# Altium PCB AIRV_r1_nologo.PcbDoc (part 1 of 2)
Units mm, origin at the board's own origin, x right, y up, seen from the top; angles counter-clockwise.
Board outline 65 x 30 mm, 4 copper layers (Top Layer, GND, MidLayer1, Bottom Layer), stack 0.732 mm thick; 130 components, 121 nets, 598 pads, 392 vias.
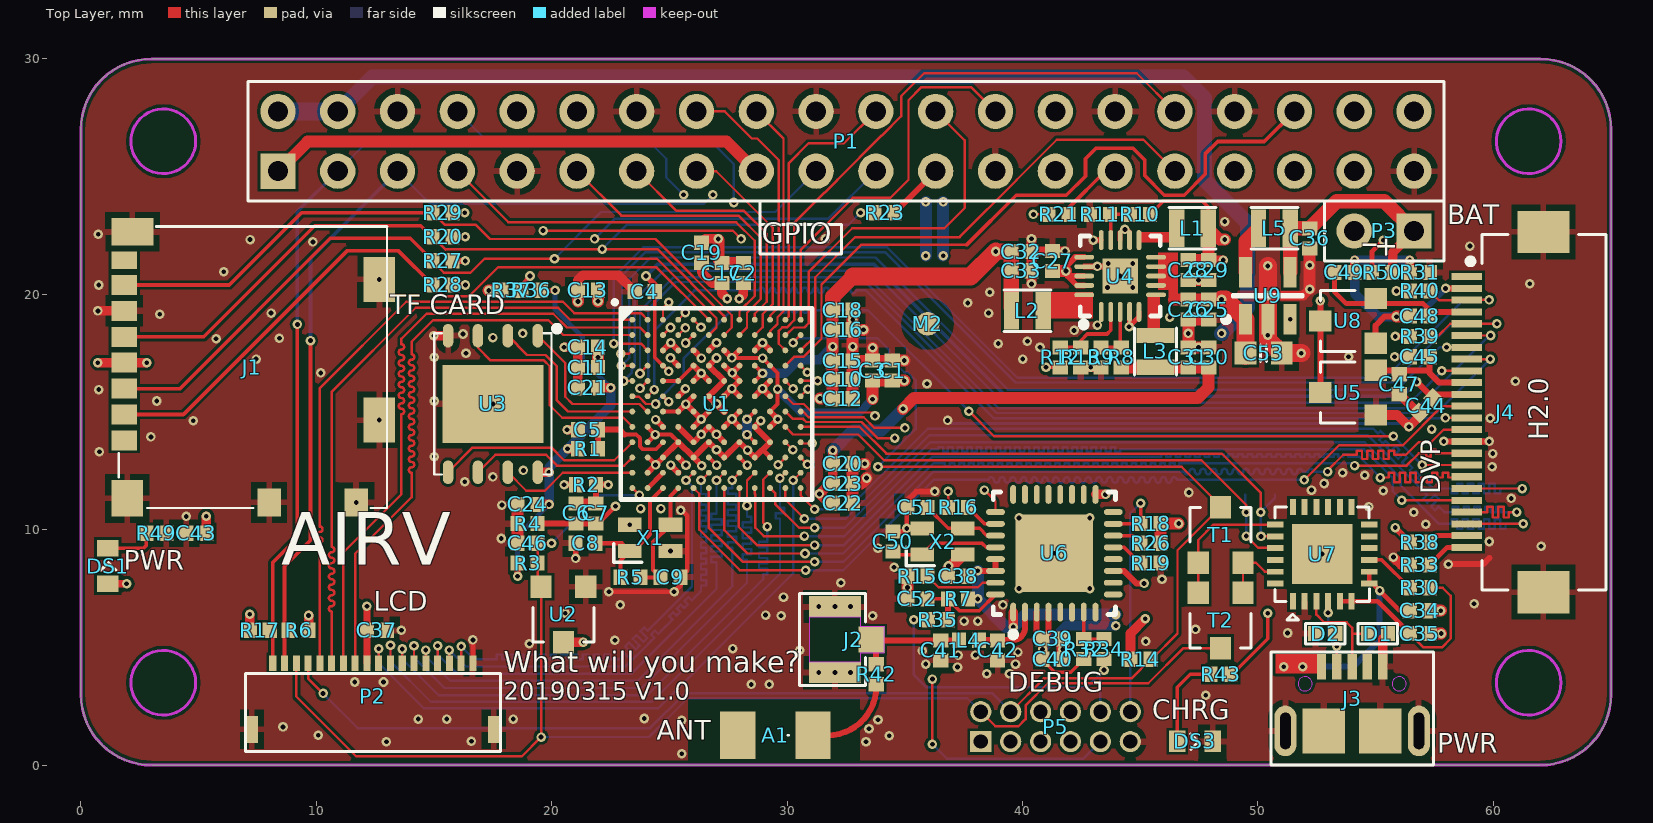
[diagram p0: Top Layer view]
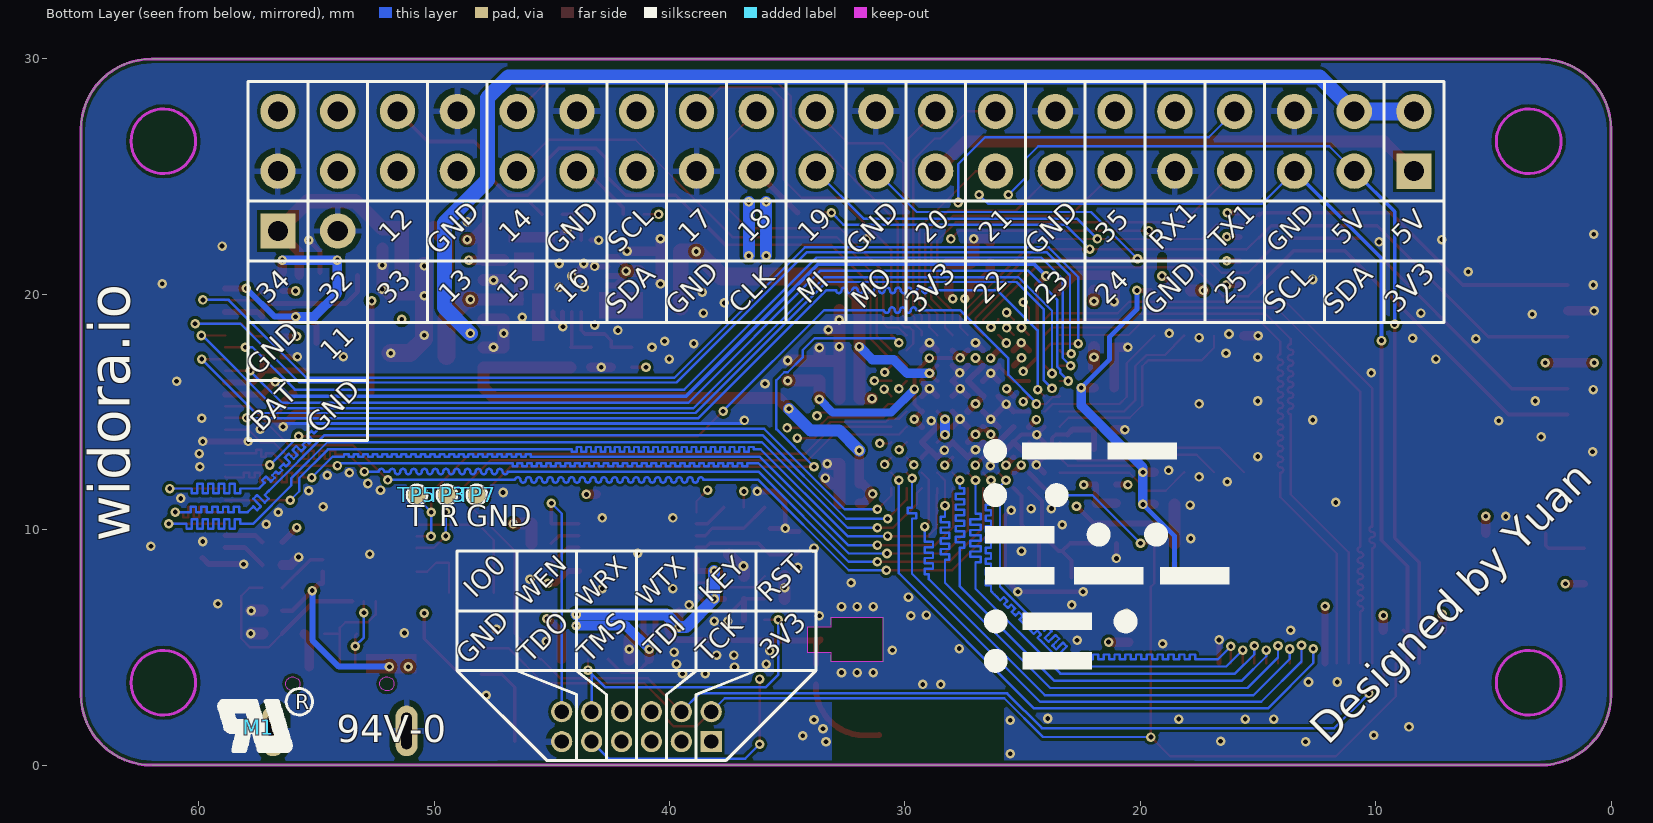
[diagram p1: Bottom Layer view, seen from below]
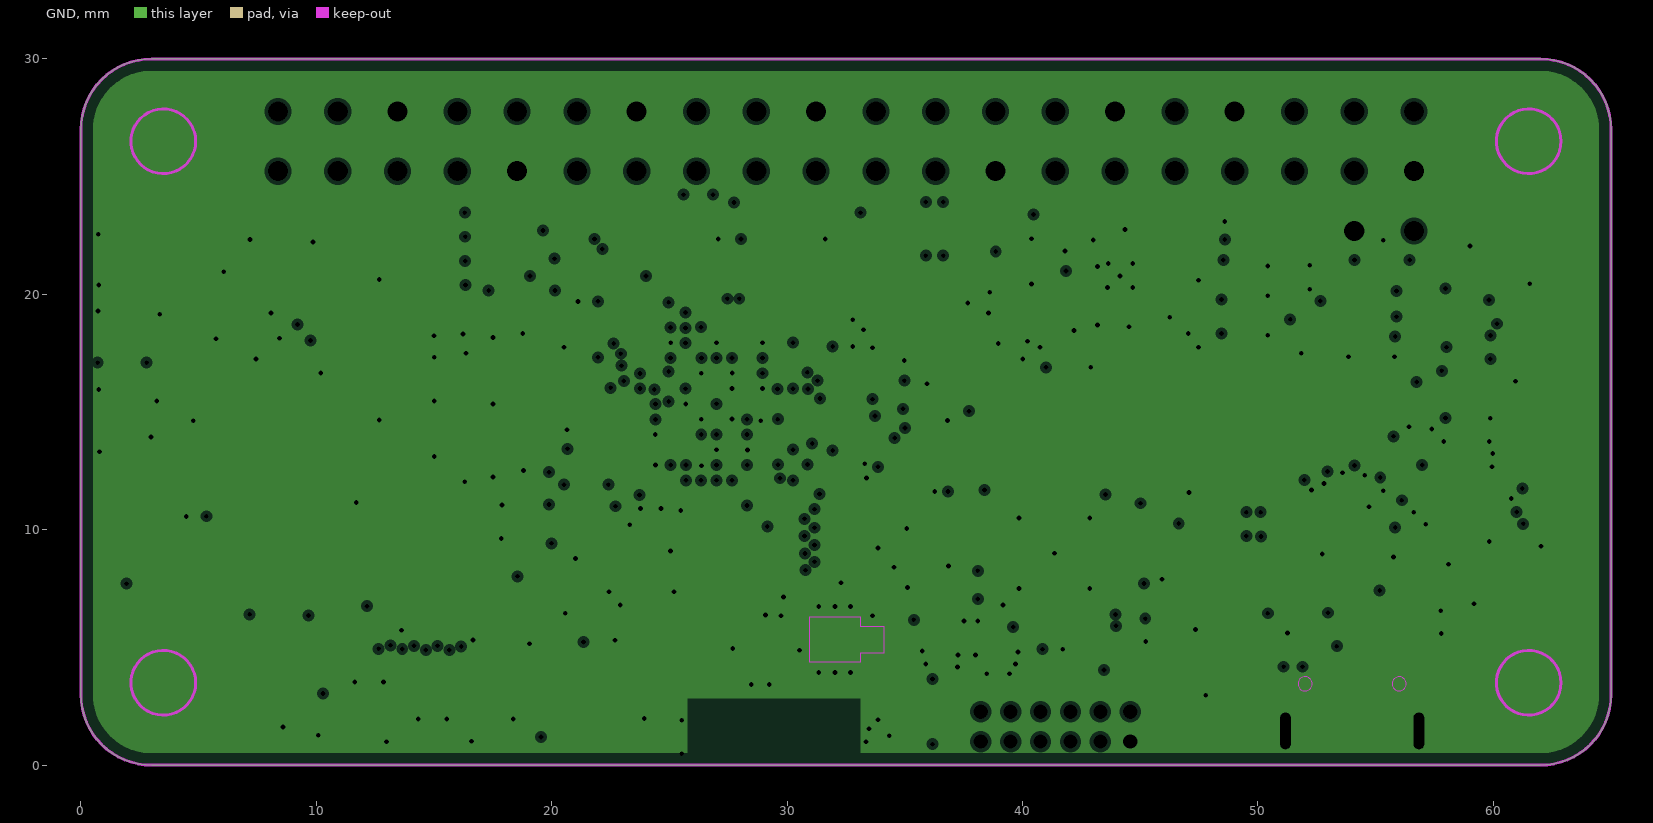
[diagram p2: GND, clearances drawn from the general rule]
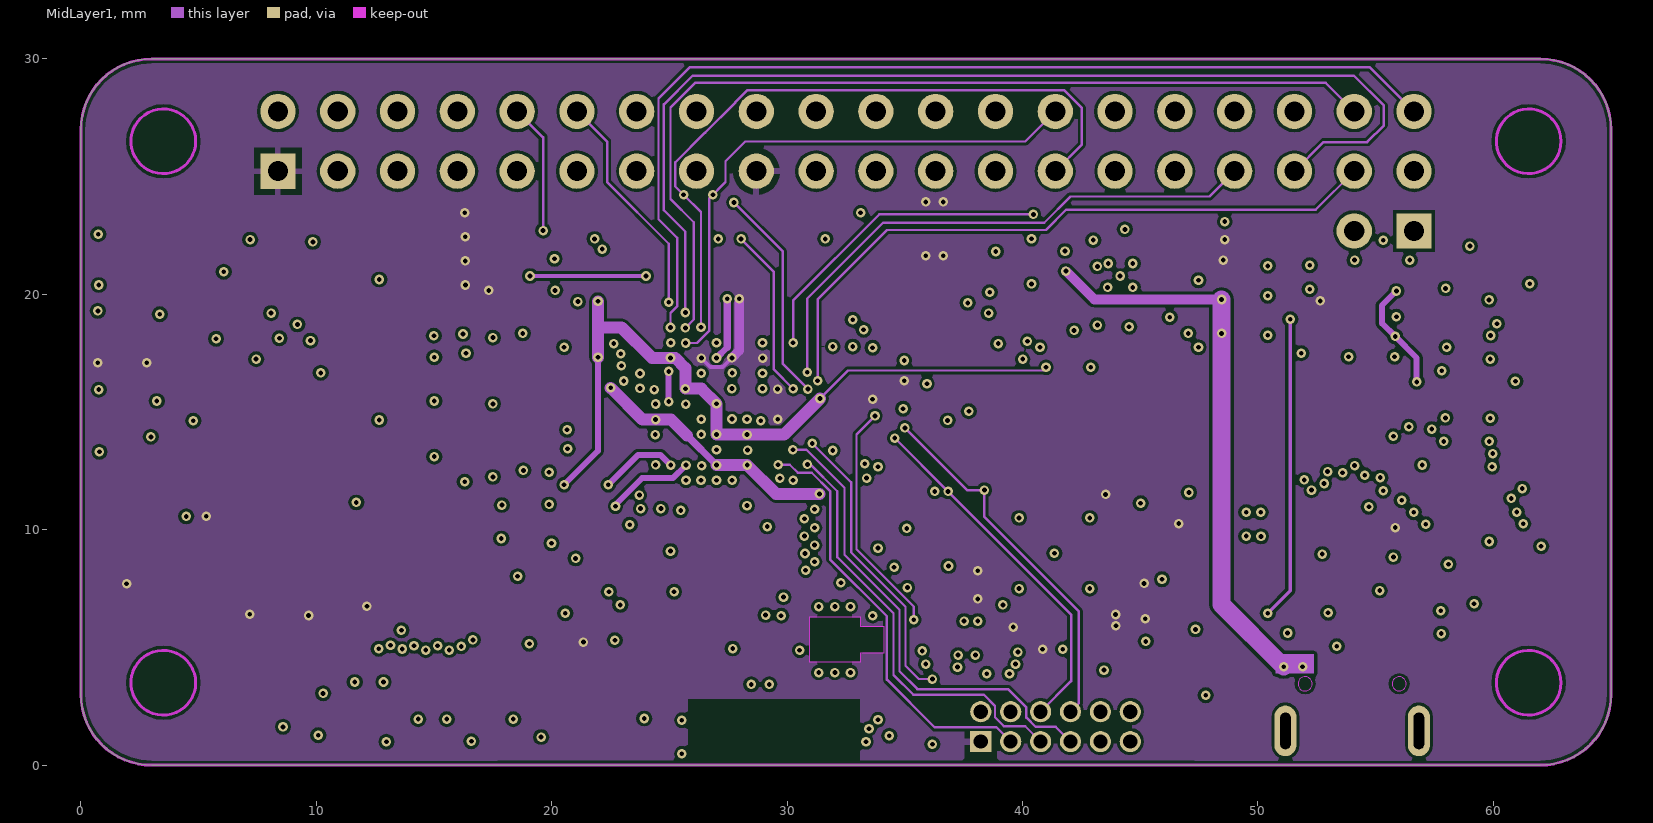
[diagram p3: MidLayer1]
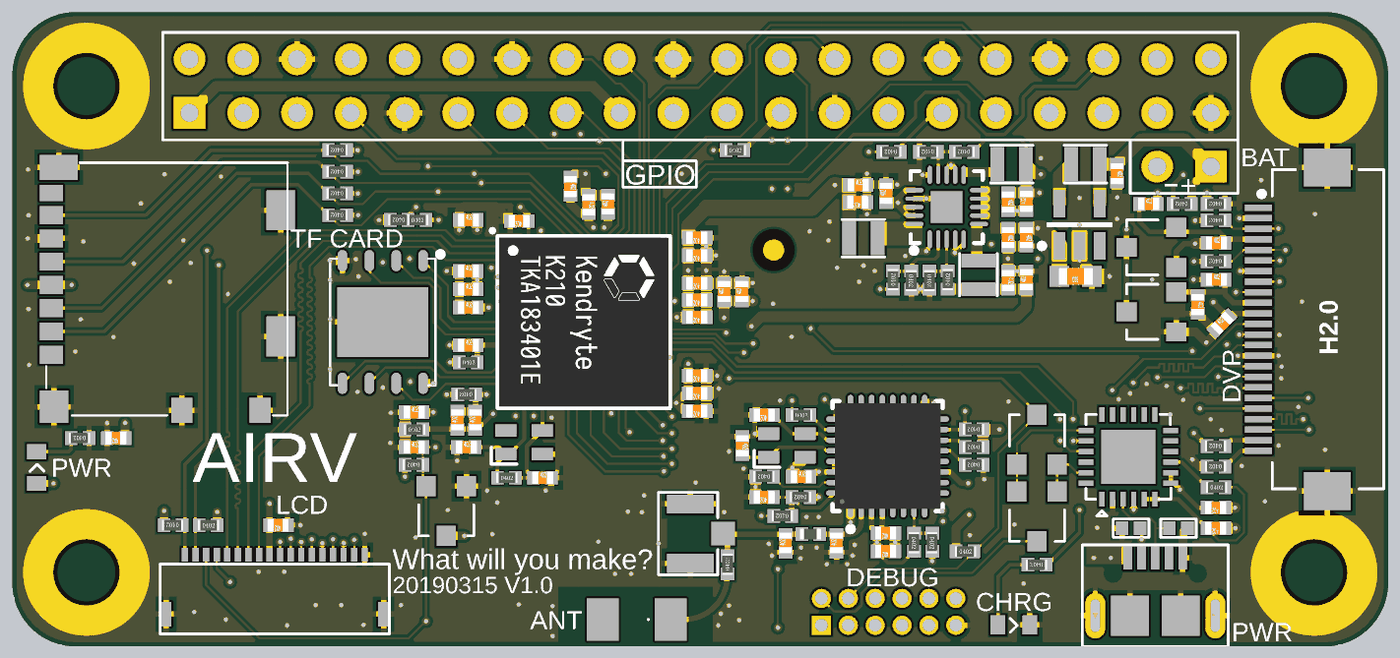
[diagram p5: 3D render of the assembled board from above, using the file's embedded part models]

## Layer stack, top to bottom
Top Layer: signal copper 0.0356
Dielectric: core 0.193, FR-4, Dk 4.8
GND: plane copper 0.0356, net GND
Dielectric: prepreg 0.2032, FR-4, Dk 4.8
MidLayer1: signal copper 0.0356
Dielectric: core 0.193, FR-4, Dk 4.8
Bottom Layer: signal copper 0.0356

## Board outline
0,3 ccw(c3,3) 3,0 62,0 ccw(c62,3) 65,3 65,27 ccw(c62,27) 62,30 3,30 ccw(c3,27) 0,27

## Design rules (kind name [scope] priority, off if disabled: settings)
AssemblyTestPointUsage [All] p1 off:
AssemblyTestpoint [All] p1 off: testpointundercomponent=TRUE minsize=1.016 maxsize=2.54 preferedsize=1.524 minholesize=0 maxholesize=1.016 preferedholesize=0.813 testpointgrid=0.025 usegrid=TRUE gridtolerance=0 allowsidetop=TRUE allowsidebottom=TRUE
Clearance Clearance_Polygon [InPolygon] p1: gap=0.127
Clearance [All] p2: gap=0.102
ComponentClearance [All] p1 off: gap=0.025 collisioncheckmode=3 verticalgap=0.025 showdistances=FALSE
DiffPairsRouting [All] p1: maxlimit=0.508 minlimit=0.102 mostfreqgap=0.127 maxuncoupledlength=76.2
FabricationTestPointUsage TestPointUsage [All] p1 off: valid=0 allowmultiple=FALSE
FabricationTestpoint Testpoint [(IsPad And (OnTopLayer Or OnBottomLayer))] p1 off: side=3 testpointundercomponent=TRUE minsize=1.016 maxsize=2.54 preferedsize=1.524 minholesize=0 maxholesize=1.016 preferedholesize=0.813 testpointgrid=0.025 allowsidetop=TRUE allowsidebottom=TRUE usegrid=TRUE gridtolerance=0
Height [All] p1 off: minheight=0 maxheight=25.4 prefheight=12.7
HoleSize [All] p1: absolutevalues=TRUE maxlimit=3.81 minlimit=0.025 maxpercent=80.000 minpercent=20.000
MinimumSolderMaskSliver [All] p1 off: minsoldermaskwidth=0.025
PlaneClearance [All] p1: clearance=0.152
PlaneConnect [All] p1: planeconnectstyle=Direct reliefexpansion=0.508 reliefentries=4 reliefconductorwidth=0.635 reliefairgap=0.254
PolygonConnect PolygonConnect_1 [All vs IsPad] p1: connectstyle=Relief reliefconductorwidth=0.254 reliefentries=4 polygonreliefangle="90 Angle"
PolygonConnect PolygonConnect_isvia [All vs IsVia] p2: connectstyle=Direct reliefconductorwidth=0.254 reliefentries=4 polygonreliefangle="90 Angle"
PolygonConnect [All] p3: connectstyle=Direct reliefconductorwidth=0.203 reliefentries=4 polygonreliefangle="90 Angle"
RoutingVias [All] p1: holewidth=0.203 width=0.406 viastyle="Through Hole" minholewidth=0.203 minwidth=0.406 maxholewidth=2.54 maxwidth=2.54
ShortCircuit [InNet('WIFI') vs InNet('GND')] p1 off: allowed=FALSE
SilkToSilkClearance [All] p1: silktosilkclearance=0
SilkscreenOverComponentPads [IsPad] p1: minsilkscreentomaskgap=0
SolderMaskExpansion [All] p1: expansion=0.102
Width [All] p1: maxlimit=2.54 minlimit=0.102 preferedwidth=0.127
14 further rules are at their usual default settings.

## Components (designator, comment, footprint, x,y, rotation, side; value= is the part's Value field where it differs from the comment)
A1 "WIFI天线" AN3216 29.5,1.27 r180 top locked
C1 "0.1uF" C0402 34.468,16.764 r90 top
C2 "0.1uF" C0402 28.143,20.904 r90 top
C3 "0.1uF" C0402 33.63,16.764 r90 top
C4 "0.1uF" C0402 23.952,20.117 r180 top
C5 "0.1uF" C0402 21.539,14.249 r0 top
C6 "4.7uF" C0402 21.031,10.693 r90 top
C7 "0.1uF" C0402 21.869,10.693 r90 top
C8 "10pF" C0402 21.438,9.423 r0 top
C9 "10pF" C0402 25.044,7.976 r0 top
C10 "4.7uF" C0402 32.36,16.383 r180 top
C11 "4.7uF" C0402 21.539,16.891 r0 top
C12 "0.1uF" C0402 32.36,15.57 r180 top
C13 "0.1uF" C0402 21.539,20.168 r0 top
C14 "0.1uF" C0402 21.539,17.755 r0 top
C15 "0.1uF" C0402 32.36,17.17 r180 top
C16 "0.1uF" C0402 32.36,18.491 r180 top
C17 "0.1uF" C0402 27.229,20.904 r270 top
C18 "0.1uF" C0402 32.36,19.329 r180 top
C19 "0.1uF" C0402 26.365,21.768 r270 top
C20 "4.7uF" C0402 32.36,12.802 r180 top
C21 "0.1uF" C0402 21.539,16.027 r0 top
C22 "0.1uF" C0402 32.36,11.125 r180 top
C23 "0.1uF" C0402 32.36,11.963 r180 top
C24 "0.1uF" C0402 18.974,11.074 r0 top
C25 "10uF" C0402 47.904,19.355 r270 top
C26 "10uF" C0402 47.041,19.355 r270 top
C27 "10uF" C0402 41.275,21.412 r90 top
C28 "10uF" C0402 47.041,21.031 r270 top
C29 "0.1uF" C0402 47.904,21.031 r90 top
C30 "10uF" C0402 47.904,17.323 r90 top
C31 "0.1uF" C0402 47.041,17.323 r270 top
C32 "10uF" C0402 39.954,21.819 r0 top
C33 "0.1uF" C0402 39.954,21.006 r180 top
C34 "10uF" C0402 56.871,6.56 r180 top
C35 "10uF" C0402 56.871,5.588 r180 top
C36 "10uF" C0402 52.197,22.377 r270 top
C37 "0.1uF" C0402 12.573,5.731 r180 top
C38 "1uF" C0402 37.262,8.026 r0 top
C39 "0.1uF" C0402 41.275,5.359 r180 top
C40 "10uF" C0402 41.275,4.496 r180 top
C41 "2.4pF" C0402 36.525,4.877 r90 top
C42 "3.0pF" C0402 38.938,4.877 r90 top
C43 "0.1uF" C0402 4.902,9.855 r180 top
C44 "0.1uF" C0402 57.15,15.272 r45 top
C45 "0.1uF" C0402 56.871,17.348 r0 top
C46 "0.1uF" C0402 18.974,9.423 r0 top
C47 "10uF" C0402 56.007,16.18 r270 top
C48 "0.1uF" C0402 56.871,19.075 r0 top
C49 "10uF" C0402 53.67,20.93 r0 top
C50 "10pF" C0402 34.493,9.5 r270 top
C51 "10pF" C0402 35.535,10.947 r180 top
C52 "0.1uF" C0402 35.535,7.061 r180 top
C53 "22uF" C0603 50.241,17.501 r180 top
D1 "TVS0402" 0402TVS 55.093,5.588 r180 top
D2 "TVS0402" 0402TVS 52.857,5.588 r0 top
DS1 "LED" LED0603 1.143,8.458 r90 top
DS3 "LED" LED0603 47.32,1.016 r0 top
J1 "TF1040310811" TFCARD-1040310811 1.6,16.9 r270 top locked
J2 "NC" "I-PEX SOCKET" 32.029,5.334 r90 top locked
J3 "MICRO_USB" MICROUSB 54,2.4 r0 top locked
J4 "OV2640" FFC/SM0.5-2H24-OV5640 60.5,15 r90 top locked
L1 "2.2uH" VLS2016 47.219,22.809 r180 top
L2 "2.2uH" VLS2016 40.208,19.304 r0 top
L3 "2.2uH" VLS2016 45.644,17.577 r90 top
L4 "2.2nH" L0402 37.719,5.309 r180 top
L5 "2.2uH" VLS2016 50.698,22.809 r0 top locked
M1 "mark" ZY_UR-3X2 57.45,1.6 r180 bottom
M2 "mark" MARKER-C 35.966,18.745 r0 top
P1 "Header 20X2" HDR2X20 8.37,25.23 r0 top locked
P2 "Header 18_ffc" FFC/SM0.5-1H18 12.4,3 r0 top locked
P3 "Header 2 RUN" HDR1X2 56.63,22.69 r180 top locked
P5 "Header 6X2" HDR1.27-6X2 38.225,1 r0 top locked
R1 "0R" R0402 21.539,13.437 r0 top
R2 "0R" R0402 21.463,11.913 r180 top
R3 "10K" R0402 18.974,8.585 r180 top
R4 "0R" R0402 18.974,10.262 r0 top
R5 "1M" R0402 23.343,7.976 r0 top
R6 "2.2K" R0402 9.246,5.731 r0 top
R7 "10K" R0402 37.262,7.061 r180 top
R8 "200K 1%" R0402 44.196,17.323 r90 top
R9 "100K 1%" R0402 43.332,17.323 r270 top
R10 "453K 1%" R0402 44.983,23.393 r180 top
R11 "100K 1%" R0402 43.282,23.393 r180 top
R12 "68K 1%" R0402 41.605,17.323 r90 top
R13 "100K 1%" R0402 42.469,17.323 r270 top
R14 "10K" R0402 45.009,4.496 r0 top
R15 "12K 1%" R0402 35.535,8.026 r180 top
R16 "499" R0402 37.262,10.947 r0 top
R17 "2.2K" R0402 7.595,5.731 r180 top
R18 "5.1K" R0402 45.441,10.262 r180 top
R19 "5.1K" R0402 45.441,8.585 r180 top
R20 "10K" R0402 15.367,22.445 r180 top
R21 "499" R0402 41.529,23.393 r180 top
R23 "22R" R0402 34.138,23.47 r0 top
R26 "5.1K" R0402 45.441,9.423 r180 top
R27 "10K" R0402 15.367,21.421 r180 top
R28 "10K" R0402 15.367,20.396 r180 top
R29 "10K" R0402 15.367,23.47 r180 top
R30 "10K" R0402 56.871,7.531 r0 top
R31 "0R" R0402 56.871,20.93 r180 top
R32 "10K" R0402 42.596,4.928 r270 top
R33 "NC" R0402 56.871,8.503 r180 top
R34 "NC" R0402 43.459,4.928 r270 top
R35 "0R" R0402 36.398,6.172 r180 top
R36 "0R" R0402 19.119,20.168 r0 top
R37 "NC" R0402 18.281,20.168 r180 top
R38 "NC" R0402 56.871,9.474 r180 top
R39 "2K" R0402 56.871,18.212 r180 top
R40 "2K" R0402 56.871,20.142 r180 top
R42 "0R" R0402 33.782,3.861 r90 top
R43 "1K" R0402 48.412,3.861 r180 top
R49 "1K" R0402 3.2,9.855 r180 top
R50 "NC" R0402 55.27,20.93 r180 top
T1 "MOS-N" SOT23 48.412,9.779 r0 top
T2 "MOS-N" SOT23 48.412,6.147 r180 top
TP3 "TEST POINT" TEST-POINT 49.454,11.481 r90 bottom
TP5 "TEST POINT" TEST-POINT 50.724,11.481 r90 bottom
TP7 "TEST POINT" TEST-POINT 48.184,11.481 r90 bottom
U1 "K210" BGA144C65P12X12_800X800X95 26.999,15.344 r0 top locked
U2 "MAX803" SOT23 20.498,6.401 r180 top
U3 "W25Q128FWP" WSON6X5 17.501,15.344 r270 top locked
U4 "EA3036" QFN40P300X300X80_HS-21N 44.145,20.777 r90 top locked
U5 "XC6206-1.5" SOT23 53.823,15.824 r90 top
U6 "ESP8285" QFN32 41.351,9 r90 top locked
U7 "CP2102N" QFN24 52.73,8.966 r90 top locked
U8 "XC6206-2.8" SOT23 53.823,18.872 r90 top
U9 "ETA6093" SOT23-5 50.419,19.939 r90 top locked
X1 "XTAL2520-26M" XTAL2520 24.181,9.652 r180 top
X2 "XTAL2520-26M" XTAL2520 36.601,9.5 r180 top

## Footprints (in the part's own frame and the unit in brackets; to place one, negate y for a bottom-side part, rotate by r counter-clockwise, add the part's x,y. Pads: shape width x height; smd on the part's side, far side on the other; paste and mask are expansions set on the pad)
0402TVS [mm]
  rect 0.6x0.65 smd mask+0.051: 1(-0.425,0) 2(0.425,0)
  silkscreen extent -0.84,-0.43 0.84,0.43
AN3216 [mm] "AN3216"
  rect 1.5x2 smd: 1(-1.6,0) 2(1.6,0)
  silkscreen extent -0.56,0 -0.53,0
BGA144C65P12X12_800X800X95 [mm] "BGA, 144-Leads, Body 8.00x8.00mmx0.95mm, Pitch 0.65mm"
  round 0.25 smd: A1(-3.575,3.575) A2(-2.925,3.575) A3(-2.275,3.575) A4(-1.625,3.575) A5(-0.975,3.575) A6(-0.325,3.575) A7(0.325,3.575) A8(0.975,3.575) A9(1.625,3.575) A10(2.275,3.575) A11(2.925,3.575) A12(3.575,3.575) B1(-3.575,2.925) B2(-2.925,2.925) B3(-2.275,2.925) B4(-1.625,2.925) B5(-0.975,2.925) B6(-0.325,2.925) B7(0.325,2.925) B8(0.975,2.925) B9(1.625,2.925) B10(2.275,2.925) B11(2.925,2.925) B12(3.575,2.925) C1(-3.575,2.275) C2(-2.925,2.275) C3(-2.275,2.275) C4(-1.625,2.275) C5(-0.975,2.275) C6(-0.325,2.275) C7(0.325,2.275) C8(0.975,2.275) C9(1.625,2.275) C10(2.275,2.275) C11(2.925,2.275) C12(3.575,2.275) D1(-3.575,1.625) D2(-2.925,1.625) D3(-2.275,1.625) D4(-1.625,1.625) D5(-0.975,1.625) D6(-0.325,1.625) D7(0.325,1.625) D8(0.975,1.625) D9(1.625,1.625) D10(2.275,1.625) D11(2.925,1.625) D12(3.575,1.625) E1(-3.575,0.975) E2(-2.925,0.975) E3(-2.275,0.975) E4(-1.625,0.975) E5(-0.975,0.975) E6(-0.325,0.975) E7(0.325,0.975) E8(0.975,0.975) E9(1.625,0.975) E10(2.275,0.975) E11(2.925,0.975) E12(3.575,0.975) F1(-3.575,0.325) F2(-2.925,0.325) F3(-2.275,0.325) F4(-1.625,0.325) F5(-0.975,0.325) F6(-0.325,0.325) F7(0.325,0.325) F8(0.975,0.325) F9(1.625,0.325) F10(2.275,0.325) F11(2.925,0.325) F12(3.575,0.325) G1(-3.575,-0.325) G2(-2.925,-0.325) G3(-2.275,-0.325) G4(-1.625,-0.325) G5(-0.975,-0.325) G6(-0.325,-0.325) G7(0.325,-0.325) G8(0.975,-0.325) G9(1.625,-0.325) G10(2.275,-0.325) G11(2.925,-0.325) G12(3.575,-0.325) H1(-3.575,-0.975) H2(-2.925,-0.975) H3(-2.275,-0.975) H4(-1.625,-0.975) H5(-0.975,-0.975) H6(-0.325,-0.975) H7(0.325,-0.975) H8(0.975,-0.975) H9(1.625,-0.975) H10(2.275,-0.975) H11(2.925,-0.975) H12(3.575,-0.975) J1(-3.575,-1.625) J2(-2.925,-1.625) J3(-2.275,-1.625) J4(-1.625,-1.625) J5(-0.975,-1.625) J6(-0.325,-1.625) J7(0.325,-1.625) J8(0.975,-1.625) J9(1.625,-1.625) J10(2.275,-1.625) J11(2.925,-1.625) J12(3.575,-1.625) K1(-3.575,-2.275) K2(-2.925,-2.275) K3(-2.275,-2.275) K4(-1.625,-2.275) K5(-0.975,-2.275) K6(-0.325,-2.275) K7(0.325,-2.275) K8(0.975,-2.275) K9(1.625,-2.275) K10(2.275,-2.275) K11(2.925,-2.275) K12(3.575,-2.275) L1(-3.575,-2.925) L2(-2.925,-2.925) L3(-2.275,-2.925) L4(-1.625,-2.925) L5(-0.975,-2.925) L6(-0.325,-2.925) L7(0.325,-2.925) L8(0.975,-2.925) L9(1.625,-2.925) L10(2.275,-2.925) L11(2.925,-2.925) L12(3.575,-2.925) M1(-3.575,-3.575) M2(-2.925,-3.575) M3(-2.275,-3.575) M4(-1.625,-3.575) M5(-0.975,-3.575) M6(-0.325,-3.575) M7(0.325,-3.575) M8(0.975,-3.575) M9(1.625,-3.575) M10(2.275,-3.575) M11(2.925,-3.575) M12(3.575,-3.575)
  silkscreen extent -4.39,-4.06 4.06,4.39, body extent -4,-4 4,4, height 0.95
C0402 [mm]
  rect 0.6x0.65 smd mask+0.051: 1(-0.425,0) 2(0.425,0)
  body extent -0.48,-0.3 0.52,0.3, height 0.2
C0603 [mm]
  rect 0.93x0.98 smd: 1(-0.77,0) 2(0.77,0)
  silkscreen extent -0.13,-0.35 0.13,0.35, body extent -0.8,-0.4 0.8,0.4, height 0.3
FFC/SM0.5-1H18 [mm] "Connector; FH12 Series; 18 Position; 0.5mm Spaced Bottom Contact"
  rect 0.3x0.65 smd: 1(-4.25,1.333) 2(-3.75,1.333) 3(-3.25,1.333) 4(-2.75,1.333) 5(-2.25,1.333) 6(-1.75,1.333) 7(-1.25,1.333) 8(-0.75,1.333) 9(-0.25,1.333) 10(0.25,1.333) 11(0.75,1.333) 12(1.25,1.333) 13(1.75,1.333) 14(2.25,1.333) 15(2.75,1.333) 16(3.25,1.333) 17(3.75,1.333) 18(4.25,1.333)
  rect 0.5x1.15 smd: G(-5.135,-1.477) G(5.135,-1.477)
  silkscreen extent -5.42,-2.41 5.42,0.89
FFC/SM0.5-2H24-OV5640 [mm] "Connector; FH12 Series; 24 Position; 0.5mm Spaced Bottom Contact"
  rect 0.3x1.3 smd: 1(5.75,1.625) 2(5.25,1.625) 3(4.75,1.625) 4(4.25,1.625) 5(3.75,1.625) 6(3.25,1.625) 7(2.75,1.625) 8(2.25,1.625) 9(1.75,1.625) 10(1.25,1.625) 11(0.75,1.625) 12(0.25,1.625) 13(-0.25,1.625) 14(-0.75,1.625) 15(-1.25,1.625) 16(-1.75,1.625) 17(-2.25,1.625) 18(-2.75,1.625) 19(-3.25,1.625) 20(-3.75,1.625) 21(-4.25,1.625) 22(-4.75,1.625) 23(-5.25,1.625) 24(-5.75,1.625)
  rect 1.8x2.2 smd: P0(-7.65,-1.625) P0(7.65,-1.625)
  silkscreen extent -7.55,-4.29 7.55,1.6
HDR1.27-6X2 [mm]
  rect 0.9x0.9 hole 0.6: 1(0,0)
  round 0.9 hole 0.6: 2(0,1.27) 3(1.27,0) 4(1.27,1.27) 5(2.54,0) 6(2.54,1.27) 7(3.81,0) 8(3.81,1.27) 9(5.08,0) 10(5.08,1.27) 11(6.35,0) 12(6.35,1.27)
HDR1X2 [mm]
  rect 1.5x1.5 hole 0.85: 1(0,0)
  round 1.5 hole 0.85: 2(2.54,0)
  silkscreen extent -1.27,-1.27 3.81,1.27
HDR2X20 [mm]
  rect 1.5x1.5 hole 0.85: 1(0,0)
  round 1.5 hole 0.85: 2(0,2.54) 3(2.54,0) 4(2.54,2.54) 5(5.08,0) 6(5.08,2.54) 7(7.62,0) 8(7.62,2.54) 9(10.16,0) 10(10.16,2.54) 11(12.7,0) 12(12.7,2.54) 13(15.24,0) 14(15.24,2.54) 15(17.78,0) 16(17.78,2.54) 17(20.32,0) 18(20.32,2.54) 19(22.86,0) 20(22.86,2.54) 21(25.4,0) 22(25.4,2.54) 23(27.94,0) 24(27.94,2.54) 25(30.48,0) 26(30.48,2.54) 27(33.02,0) 28(33.02,2.54) 29(35.56,0) 30(35.56,2.54) 31(38.1,0) 32(38.1,2.54) 33(40.64,0) 34(40.64,2.54) 35(43.18,0) 36(43.18,2.54) 37(45.72,0) 38(45.72,2.54) 39(48.26,0) 40(48.26,2.54)
  silkscreen extent -1.27,-1.27 49.53,3.81
"I-PEX SOCKET" [mm]
  rect 1.1x1.1 smd: 1(0,-1.55)
  rect 0.9x2.2 smd: 2(1.4,0) 3(-1.4,0)
  Keep-Out Layer pour cut-out: -0.95,1.1 -0.95,-1.101 -0.551,-1.101 -0.551,-2.101 0.001,-2.101 0.55,-2.101 0.55,-1.101 0.95,-1.101 0.95,1.1
  silkscreen extent -1.95,-1.3 1.95,1.5
L0402 [mm]
  rect 0.6x0.65 smd mask+0.051: 1(-0.425,0) 2(0.425,0)
  body extent -0.51,-0.26 0.54,0.26, height 0.36
LED0603 [mm]
  rect 0.7x0.9 smd: A(-0.75,0) K(0.75,0)
  silkscreen extent -0.18,-0.34 0.15,0.3
MARKER-C [mm]
  round 1 smd paste-1.016 mask+0.5: 0(0,0)
  Top Layer pour cut-out: -1.109,0 -1.072,-0.287 -0.961,-0.555 -0.785,-0.785 -0.555,-0.961 -0.287,-1.072 0,-1.109 0,-1.109 0.287,-1.072 0.555,-0.961 0.785,-0.785 0.961,-0.555 1.072,-0.287 1.109,0 1.109,0 1.072,0.287 0.961,0.555 0.785,0.785 0.555,0.961 0.287,1.072 0,1.109 0,1.109 -0.287,1.072 -0.555,0.961 -0.785,0.785 -0.961,0.555 -1.072,0.287 -1.109,0
MICROUSB [mm] "MICROUSB"
  rect 0.4x1.1 smd: 1(-1.3,1.78) 2(-0.65,1.78) 3(0,1.78) 4(0.65,1.78) 5(1.3,1.78)
  oval 0.94x2.15 hole 0.45 slot 1.55 at 90 deg: 6(-2.835,-0.946) 7(2.835,-0.946)
  rect 1.8x1.9 smd: 8(-1.2,-0.946) 9(1.2,-0.946)
  Keep-Out Layer circle w0.025: c-2,1.054 r0.3
  Keep-Out Layer circle w0.025: c2,1.054 r0.3
  silkscreen extent -3.45,-2.4 3.45,2.4
QFN24 [mm]
  rect 0.7x0.25 smd: 1(-2,1.25) 2(-2,0.75) 3(-2,0.25) 4(-2,-0.25) 5(-2,-0.75) 6(-2,-1.25) 13(2,-1.25) 14(2,-0.75) 15(2,-0.25) 16(2,0.25) 17(2,0.75) 18(2,1.25)
  rect 0.25x0.7 smd: 7(-1.25,-2) 8(-0.75,-2) 9(-0.25,-2) 10(0.25,-2) 11(0.75,-2) 12(1.25,-2) 19(1.25,2) 20(0.75,2) 21(0.25,2) 22(-0.25,2) 23(-0.75,2) 24(-1.25,2)
  rect 2.55x2.55 smd: 25(0,0)
  silkscreen extent -2.79,-2.01 2.01,2.01
QFN32 [mm] "32-Pin Quad Flat No-Lead 0.5 mm Pitch, IPC High Density"
  oval 0.8x0.25 smd: 1(-2.5,1.75) 2(-2.5,1.25) 3(-2.5,0.75) 4(-2.5,0.25) 5(-2.5,-0.25) 6(-2.5,-0.75) 7(-2.5,-1.25) 8(-2.5,-1.75) 17(2.5,-1.75) 18(2.5,-1.25) 19(2.5,-0.75) 20(2.5,-0.25) 21(2.5,0.25) 22(2.5,0.75) 23(2.5,1.25) 24(2.5,1.75)
  oval 0.25x0.8 smd: 9(-1.75,-2.5) 10(-1.25,-2.5) 11(-0.75,-2.5) 12(-0.25,-2.5) 13(0.25,-2.5) 14(0.75,-2.5) 15(1.25,-2.5) 16(1.75,-2.5) 25(1.75,2.5) 26(1.25,2.5) 27(0.75,2.5) 28(0.25,2.5) 29(-0.25,2.5) 30(-0.75,2.5) 31(-1.25,2.5) 32(-1.75,2.5)
  rect 3.3x3.3 smd paste-2.54: 33(0,0)
  silkscreen extent -3.57,-2.6 2.6,2.6, body extent -2.51,-2.51 2.51,2.51, height 0.8
QFN40P300X300X80_HS-21N [mm] "QFN, 20-Leads, Body 3.00x3.00mm, Pitch 0.40mm, Thermal Pad 1.65x1.65mm, IPC Medium Density"
  oval 0.85x0.2 smd: 1(-1.525,0.8) 2(-1.525,0.4) 3(-1.525,0) 4(-1.525,-0.4) 5(-1.525,-0.8) 11(1.525,-0.8) 12(1.525,-0.4) 13(1.525,0) 14(1.525,0.4) 15(1.525,0.8)
  oval 0.2x0.85 smd: 6(-0.8,-1.525) 7(-0.4,-1.525) 8(0,-1.525) 9(0.4,-1.525) 10(0.8,-1.525) 16(0.8,1.525) 17(0.4,1.525) 18(0,1.525) 19(-0.4,1.525) 20(-0.8,1.525)
  rect 1.5x1.5 smd: 21(0,0)
  silkscreen extent -2.18,-1.7 1.7,1.7, body extent -1.55,-1.55 1.55,1.55, height 0.8
R0402 [mm]
  rect 0.6x0.65 smd mask+0.051: 1(-0.425,0) 2(0.425,0)
  body extent -0.47,-0.25 0.53,0.25, height 0.35
SOT23 [mm] "SOT-23; 3 Leads; Body 3.0 x 2.5 mm, inc. leads (LxW max)"
  rect 0.9x0.95 smd: 1(-0.95,-1.175) 2(0.95,-1.175) 3(0,1.175)
  silkscreen extent -1.3,-0.3 1.3,1.18
SOT23-5 [mm] "SOT23, 5-Leads, Body 3.0x2.6mm (max), Pitch 0.95mm, IPC Medium Density"
  rect 1.3x0.55 smd: 1(-1,0.95) 2(-1,0) 3(-1,-0.95) 4(1,-0.95) 5(1,0.95)
  silkscreen extent -1.12,-1.5 0.05,1.9, body extent -0.7,-1.5 0.7,1.5, height 1.1
TEST-POINT [mil]
  round 30 smd paste-15.75: 1(0,0)
  silkscreen extent -17,-17 17,17
TFCARD-1040310811 [mm] "TFCARD"
  rect 0.85x1.1 smd: 1(3.105,0.239) 2(2.005,0.239) 3(0.905,0.239) 4(-0.195,0.239) 5(-1.295,0.239) 6(-2.395,0.239) 7(-3.495,0.239)
  rect 0.75x1.1 smd: 8(-4.545,0.239)
  rect 1.55x1.35 smd: G1(5.565,0.365)
  rect 1.17x1.8 smd: G2(-5.755,0.589)
  rect 1.9x1.35 smd: G3(-3.73,11.075) G4(2.24,11.075)
  rect 1.2x1 smd: G5(5.74,10.1) G6(5.74,6.4)
  silkscreen extent -5.97,0 5.97,11.4
VLS2016 [mm] "VLS2"
  rect 0.65x1.6 smd: 1(0.675,0) 2(-0.675,0)
  silkscreen extent -1,-0.89 1,0.89
WSON6X5 [mm]
  oval 1x0.45 smd: 1(-2.9,1.905) 2(-2.9,0.635) 3(-2.9,-0.635) 4(-2.9,-1.905) 5(2.9,-1.905) 6(2.9,-0.635) 7(2.9,0.635) 8(2.9,1.905)
  rect 3.3x4.3 smd: 4(0,0)
  silkscreen extent -3.32,-2.49 3,2.84
XTAL2520 [mil] "XTAL2520"
  rect 39.37x23.62 smd: 1(34,22) 2(-34,22) 3(-34,-22) 4(34,-22)
  silkscreen extent 14,10 61,41
ZY_UR-3X2 [mm]
  silkscreen extent -1.7,-1.02 2.28,1.65

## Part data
A1: library part ANT2.4G
C1 C2 C3 C4 C5 C6 C7 C8 C9 C10 C11 C12 C13 C14 C15 C16 C17 C18 C19 C20 C21 C22 C23 C24 C25 C26 C27 C28 C29 C30 C31 C32 C33 C34 C35 C36 C37 C38 C39 C40 C41 C42 C43 C44 C45 C46 C47 C48 C49 C50 C51 C52 C53: library part CAP, "普通小"
D1 D2: library part D-TVS, "TVS放电管SMBJ5.0"
J1: library part TF5033981892
J2: library part MCX_IPEX
J4: library part OV5640, "Header, 24-Pin"
L1 L2 L3 L5: library part L, "普通电感"
L4: library part L0402
P1: "Header, 20-Pin, Dual row"
P2: "Header, 18-Pin"
P3: library part "Header 2", "Header, 2-Pin"
P5: "Header, 6-Pin, Dual row"
R1 R2 R3 R4 R5 R6 R7 R8 R9 R10 R11 R12 R13 R14 R15 R16 R17 R18 R19 R20 R21 R23 R26 R27 R28 R29 R30 R31 R32 R33 R34 R35 R36 R37 R38 R39 R40 R42 R43 R49 R50: library part RES, "ÆÕÍ¨µ"
TP3 TP5 TP7: library part TP, "Description"
U1: "Canaan Kendryte K210 AI SoC"
U2: library part MAX809
U3: library part SPIFLASH_SOP8W
U5 U8: library part XC6206
U6: library part ESP8266EX, "ESP8285 IOT SOC"
U7: library part CP2104
X1 X2: library part XTAL3225

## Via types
v1: diameter 0.406, hole 0.203, Top Layer to Bottom Layer, tented both sides, 392 vias

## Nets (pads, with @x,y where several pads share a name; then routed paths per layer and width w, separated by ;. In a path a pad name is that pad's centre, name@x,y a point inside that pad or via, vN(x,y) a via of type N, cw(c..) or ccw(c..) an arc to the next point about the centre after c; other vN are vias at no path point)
AGND: C48.1 C49.2 J4.2 R31.2 U8.1 | length 12.9
  Top Layer w0.254: U8.1@54.998,17.922 54.998,18.676 55.372,19.05 v1(55.88,19.05) ; v1(57.969,20.25) J4.2@58.875,20.25
  Top Layer w0.406: C49.2@54.095,20.93 54.102,20.936 v1(54.102,21.456) ; R31.2@56.446,20.93 v1(56.446,21.456)
  Top Layer w0.508: v1(55.88,19.05) C48.1@56.446,19.05
  Bottom Layer w0.254: v1(55.88,19.05) 56.769,19.05 v1(57.969,20.25)
  Bottom Layer w0.406: v1(55.88,19.05) 55.093,19.05 54.102,20.041 v1(54.102,21.456) v1(56.446,21.456)
AVDD2V8: C48.2 C49.1 J4.4 U8.2 | length 7
  Top Layer w0.203: C49.1@53.245,20.796 53.245,20.11 53.746,19.609 57.023,19.609 57.296,19.336 C48.2@57.296,19.05
  Top Layer w0.254: C48.2@57.296,19.05 57.496,19.25 J4.4@58.875,19.25
BAT: C36.1 L5.1 P3.1 R50.1 U9.4 | length 11.1
  Top Layer w0.406: R50.1@55.721,20.803 55.721,21.781 P3.1@56.63,22.69
  Top Layer w0.508: U9.4@51.369,20.939 51.369,21.605
  Top Layer w0.61: U9.4@51.369,20.939 51.373,20.943 L5.1@51.373,22.809 51.38,22.802 C36.1@52.197,22.802 53.347,23.952 55.368,23.952 P3.1@56.63,22.69
BOOT_KEY0: P2.4 P5.4 R14.2 R21.2 T1.3 U1.B12 | length 87.3
  Top Layer w0.102: P2.4@9.65,4.333 9.65,3.685 v1(10.287,3.048) ; v1(30.251,17.947) U1.B12@30.574,18.269 ; v1(33.858,12.675) 46.756,12.675 48.412,11.018 T1.3@48.412,10.954 46.584,9.125 46.584,5.595 45.485,4.496 R14.2@45.434,4.496 44.621,3.683 40.908,3.683 P5.4@39.495,2.27 ; v1(40.462,23.393) R21.2@41.104,23.393
  MidLayer1 w0.102: v1(30.251,17.947) 30.251,19.736 33.909,23.393 v1(40.462,23.393)
  Bottom Layer w0.102: v1(10.287,3.048) 11.76,1.575 24.181,1.575 25.654,3.048 38.717,3.048 P5.4@39.495,2.27 ; v1(30.251,17.947) 30.44,18.136 33.833,18.136 34.341,17.628 34.341,17.321 34.974,16.688 35.123,16.688 35.458,16.352 35.458,14.275 v1(33.858,12.675)
DTR: T1.2 T2.1 U7.23 | length 2.8
  Top Layer w0.102: T2.1@49.362,7.322 T1.2@49.362,8.604 49.904,8.604 50.292,8.216 U7.23@50.73,8.216
DVP-Y2: J4.19 U1.M12 | length 42.7
  Top Layer w0.102: U1.M12@30.574,11.769 30.574,11.463 v1(31.166,10.871) ; J4.19@58.875,11.75 v1(61.229,11.75)
  Bottom Layer w0.102: v1(31.166,10.871) 32.563,10.871 35.979,14.287 54.902,14.287 55.016,14.173 55.097,14.092 55.205,14.2 55.367,14.038 55.259,13.931 55.151,13.823 55.313,13.661 55.421,13.769 55.582,13.607 55.474,13.5 55.636,13.338 55.744,13.446 55.852,13.554 56.013,13.392 55.905,13.284 55.798,13.176 55.959,13.015 56.067,13.123 56.175,13.23 56.336,13.069 56.229,12.961 56.121,12.853 56.283,12.691 56.39,12.799 56.552,12.638 56.444,12.53 56.606,12.368 56.714,12.476 56.875,12.314 56.768,12.207 56.929,12.045 57.037,12.153 57.145,12.26 57.306,12.099 57.199,11.991 57.302,11.887 57.44,11.75 57.887,11.75 58.001,11.75 58.229,11.75 58.229,11.547 58.458,11.547 58.458,11.75 58.458,11.953 58.687,11.953 58.687,11.75 58.687,11.547 58.915,11.547 58.915,11.75 58.915,11.953 59.144,11.953 59.144,11.75 59.144,11.547 59.372,11.547 59.372,11.75 59.372,11.953 59.601,11.953 59.601,11.75 59.601,11.547 59.83,11.547 59.83,11.75 59.83,11.953 60.058,11.953 60.058,11.75 60.058,11.547 60.287,11.547 60.287,11.75 60.401,11.75 v1(61.229,11.75)
DVP-Y3: J4.21 U1.M11 | length 42.3
  Top Layer w0.102: U1.M11@29.924,11.769 29.924,11.275 v1(30.734,10.465) ; U1.M11@29.927,11.769 U1.M11@29.927,11.772 ; J4.21@58.875,10.75 59.632,10.75 59.747,10.75 59.747,10.979 59.975,10.979 59.975,10.75 59.975,10.521 60.204,10.521 60.204,10.75 60.204,10.979 60.432,10.979 60.432,10.75 60.432,10.521 60.661,10.521 60.661,10.75 60.89,10.75 v1(60.991,10.75)
  Bottom Layer w0.102: v1(30.734,10.465) 32.487,10.465 36.043,14.021 54.647,14.021 56.914,11.753 57.029,11.639 57.19,11.477 57.029,11.316 57.19,11.154 57.352,11.316 57.514,11.477 57.675,11.316 57.514,11.154 57.352,10.992 57.514,10.831 57.675,10.992 57.837,10.831 57.918,10.75 58.052,10.75 58.28,10.75 58.28,10.979 58.509,10.979 58.509,10.75 58.737,10.75 58.737,10.979 58.966,10.979 58.966,10.75 59.195,10.75 59.195,10.979 59.423,10.979 59.423,10.75 59.652,10.75 59.652,10.979 59.88,10.979 59.88,10.75 60.109,10.75 60.109,10.979 60.338,10.979 60.338,10.75 60.566,10.75 60.681,10.75 v1(60.991,10.75)
DVP-Y4: J4.22 U1.M10 | length 42.5
  Top Layer w0.102: U1.M10@29.277,11.772 29.489,11.56 29.489,11.1 30.505,10.084 v1(31.166,10.084) ; J4.22@58.863,10.262 J4.22@58.875,10.25 v1(61.265,10.25)
  Bottom Layer w0.102: v1(31.166,10.084) 32.436,10.084 36.068,13.716 54.534,13.716 56.058,12.192 56.058,11.887 57.695,10.25 58.115,10.25 58.229,10.25 58.229,10.453 58.458,10.453 58.458,10.25 58.458,10.047 58.687,10.047 58.687,10.25 58.687,10.453 58.915,10.453 58.915,10.25 58.915,10.047 59.144,10.047 59.144,10.25 59.144,10.453 59.372,10.453 59.372,10.25 59.372,10.047 59.601,10.047 59.601,10.25 59.601,10.453 59.83,10.453 59.83,10.25 59.83,10.047 60.058,10.047 60.058,10.25 60.058,10.453 60.287,10.453 60.287,10.25 60.287,10.047 60.515,10.047 60.515,10.25 60.579,10.25 v1(61.265,10.25)
DVP-Y5: J4.20 U1.M9 | length 42.5
  Top Layer w0.102: U1.M9@28.627,11.772 28.627,11.532 28.651,11.507 28.651,10.084 29.007,9.728 v1(30.734,9.728) ; v1(56.109,11.252) 58.873,11.252 J4.20@58.875,11.25
  Bottom Layer w0.102: v1(30.734,9.728) 32.436,9.728 36.119,13.411 36.322,13.411 36.424,13.411 36.424,13.513 36.627,13.513 36.627,13.411 36.627,13.31 36.83,13.31 36.83,13.411 36.83,13.513 37.033,13.513 37.033,13.411 37.033,13.31 37.236,13.31 37.236,13.411 37.236,13.513 37.44,13.513 37.44,13.411 37.44,13.31 37.643,13.31 37.643,13.411 37.643,13.513 37.846,13.513 37.846,13.411 37.846,13.31 38.049,13.31 38.049,13.411 38.049,13.513 38.252,13.513 38.252,13.411 38.252,13.31 38.456,13.31 38.456,13.411 38.456,13.513 38.659,13.513 38.659,13.411 38.659,13.31 38.862,13.31 38.862,13.411 38.862,13.513 39.065,13.513 39.065,13.411 39.065,13.31 39.268,13.31 39.268,13.411 39.268,13.513 39.472,13.513 39.472,13.411 39.472,13.31 39.675,13.31 39.675,13.411 39.675,13.513 39.878,13.513 39.878,13.411 39.878,13.31 40.081,13.31 40.081,13.411 40.081,13.513 40.284,13.513 40.284,13.411 40.284,13.31 40.488,13.31 40.488,13.411 40.488,13.513 40.691,13.513 40.691,13.411 40.691,13.31 40.894,13.31 40.894,13.411 40.894,13.513 41.097,13.513 41.097,13.411 41.097,13.31 41.3,13.31 41.3,13.411 41.3,13.513 41.504,13.513 41.504,13.411 41.504,13.31 41.707,13.31 41.707,13.411 41.707,13.513 41.91,13.513 41.91,13.411 41.91,13.31 42.113,13.31 42.113,13.411 42.113,13.513 42.316,13.513 42.316,13.411 42.316,13.31 42.52,13.31 42.52,13.411 42.52,13.513 42.723,13.513 42.723,13.411 42.723,13.31 42.926,13.31 42.926,13.411 42.926,13.513 43.129,13.513 43.129,13.411 43.129,13.31 43.332,13.31 43.332,13.411 43.332,13.513 43.536,13.513 43.536,13.411 43.536,13.31 43.739,13.31 43.739,13.411 43.739,13.513 43.942,13.513 43.942,13.411 43.942,13.31 44.145,13.31 44.145,13.411 44.171,13.411 54.508,13.411 55.728,12.192 55.728,11.633 v1(56.109,11.252)
DVP-Y6: J4.18 U1.M8 | length 42.6
  Top Layer w0.102: U1.M8@27.977,11.772 27.977,11.208 27.94,11.171 27.94,10.128 28.721,9.347 v1(31.166,9.347) ; v1(55.194,12.217) 55.448,12.217 55.562,12.217 55.562,12.421 55.791,12.421 55.791,12.217 55.791,12.014 56.02,12.014 56.02,12.217 56.02,12.421 56.248,12.421 56.248,12.217 56.248,12.014 56.477,12.014 56.477,12.217 56.477,12.421 56.706,12.421 56.706,12.217 56.706,12.014 56.934,12.014 56.934,12.217 57.163,12.217 57.163,12.014 57.391,12.014 57.391,12.217 57.391,12.421 57.62,12.421 57.62,12.217 57.848,12.217 57.848,12.421 58.077,12.421 58.077,12.217 58.166,12.217 58.842,12.217 J4.18@58.875,12.25
  Bottom Layer w0.102: v1(31.166,9.347) 32.41,9.347 36.17,13.106 45.796,13.106 45.898,13.106 45.898,13.208 46.101,13.208 46.101,13.106 46.304,13.106 46.304,13.208 46.507,13.208 46.507,13.106 46.711,13.106 46.711,13.208 46.914,13.208 46.914,13.106 47.117,13.106 47.117,13.208 47.32,13.208 47.32,13.106 47.523,13.106 47.523,13.208 47.727,13.208 47.727,13.106 47.93,13.106 47.93,13.208 48.133,13.208 48.133,13.106 48.336,13.106 48.336,13.208 48.539,13.208 48.539,13.106 48.743,13.106 48.743,13.208 48.946,13.208 48.946,13.106 49.149,13.106 49.149,13.208 49.352,13.208 49.352,13.106 49.555,13.106 49.555,13.208 49.759,13.208 49.759,13.106 49.962,13.106 49.962,13.208 50.165,13.208 50.165,13.106 50.368,13.106 50.368,13.208 50.571,13.208 50.571,13.106 50.775,13.106 50.775,13.208 50.978,13.208 50.978,13.106 51.181,13.106 51.181,13.208 51.384,13.208 51.384,13.106 51.587,13.106 51.587,13.208 51.791,13.208 51.791,13.106 51.994,13.106 51.994,13.208 52.197,13.208 52.197,13.106 52.4,13.106 52.4,13.208 52.603,13.208 52.603,13.106 52.807,13.106 52.807,13.208 53.01,13.208 53.01,13.106 53.213,13.106 53.213,13.208 53.416,13.208 53.416,13.106 53.619,13.106 53.619,13.208 53.823,13.208 53.823,13.106 54.026,13.106 54.127,13.106 54.305,13.106 v1(55.194,12.217)
DVP-Y7: J4.16 U1.M7 | length 42.6
  Top Layer w0.102: U1.M7@27.327,11.772 27.327,9.982 28.318,8.992 v1(30.759,8.992) ; v1(54.102,12.725) 56.312,12.725 56.836,13.25 56.938,13.25 57.141,13.25 57.141,13.098 57.344,13.098 57.344,13.25 57.344,13.402 57.548,13.402 57.548,13.25 57.607,13.25 J4.16@58.875,13.25
  Bottom Layer w0.102: v1(30.759,8.992) 32.385,8.992 36.22,12.827 36.398,12.827 36.5,12.827 36.703,12.827 36.703,12.7 36.906,12.7 36.906,12.827 37.109,12.827 37.109,12.7 37.313,12.7 37.313,12.827 37.516,12.827 37.516,12.7 37.719,12.7 37.719,12.827 37.922,12.827 37.922,12.7 38.125,12.7 38.125,12.827 38.329,12.827 38.329,12.7 38.532,12.7 38.532,12.827 38.735,12.827 38.735,12.7 38.938,12.7 38.938,12.827 39.141,12.827 39.141,12.7 39.345,12.7 39.345,12.827 39.548,12.827 39.548,12.7 39.751,12.7 39.751,12.827 39.954,12.827 39.954,12.7 40.157,12.7 40.157,12.827 40.361,12.827 40.361,12.7 40.564,12.7 40.564,12.827 40.767,12.827 40.767,12.7 40.97,12.7 40.97,12.827 41.173,12.827 41.173,12.7 41.377,12.7 41.377,12.827 41.58,12.827 41.58,12.7 41.783,12.7 41.783,12.827 41.986,12.827 41.986,12.7 42.189,12.7 42.189,12.827 42.393,12.827 42.393,12.7 42.596,12.7 42.596,12.827 42.799,12.827 42.799,12.7 43.002,12.7 43.002,12.827 43.205,12.827 43.205,12.7 43.409,12.7 43.409,12.827 43.612,12.827 43.612,12.7 43.815,12.7 43.815,12.827 44.018,12.827 44.018,12.7 44.221,12.7 44.221,12.827 44.425,12.827 44.425,12.7 44.628,12.7 44.628,12.827 44.831,12.827 44.831,12.7 45.034,12.7 45.034,12.827 45.237,12.827 45.237,12.7 45.441,12.7 45.441,12.827 45.644,12.827 45.644,12.7 45.847,12.7 45.847,12.827 46.05,12.827 46.05,12.7 46.253,12.7 46.253,12.827 46.457,12.827 46.457,12.7 46.66,12.7 46.66,12.827 46.863,12.827 54,12.827 v1(54.102,12.725)
DVP-Y8: J4.14 U1.M6 | length 42.3
  Top Layer w0.102: U1.M6@26.677,11.772 26.677,10.077 28.118,8.636 v1(31.166,8.636) ; v1(52.959,12.471) 52.959,12.522 53.619,13.183 53.734,13.183 53.962,13.183 54.191,13.183 54.191,13.36 54.419,13.36 54.419,13.183 54.419,13.005 54.648,13.005 54.648,13.183 54.648,13.36 54.877,13.36 54.877,13.183 54.877,13.005 55.105,13.005 55.105,13.183 55.105,13.36 55.334,13.36 55.334,13.183 55.334,13.005 55.562,13.005 55.562,13.183 55.562,13.36 55.791,13.36 55.791,13.183 55.931,13.183 56.286,13.183 56.82,13.716 57.353,13.716 57.887,14.25 J4.14@58.875,14.25
  Bottom Layer w0.102: v1(31.166,8.636) 32.385,8.636 36.22,12.471 46.634,12.471 46.863,12.471 ccw(c46.977,12.471) 47.092,12.471 cw(c47.206,12.471) 47.32,12.471 ccw(c47.434,12.471) 47.549,12.471 cw(c47.663,12.471) 47.777,12.471 ccw(c47.892,12.471) 48.006,12.471 cw(c48.12,12.471) 48.235,12.471 ccw(c48.349,12.471) 48.463,12.471 cw(c48.578,12.471) 48.692,12.471 ccw(c48.806,12.471) 48.92,12.471 cw(c49.035,12.471) 49.149,12.471 ccw(c49.263,12.471) 49.378,12.471 cw(c49.492,12.471) 49.606,12.471 ccw(c49.721,12.471) 49.835,12.471 cw(c49.949,12.471) 50.063,12.471 ccw(c50.178,12.471) 50.292,12.471 cw(c50.406,12.471) 50.521,12.471 ccw(c50.635,12.471) 50.749,12.471 cw(c50.863,12.471) 50.978,12.471 ccw(c51.092,12.471) 51.206,12.471 cw(c51.321,12.471) 51.435,12.471 ccw(c51.549,12.471) 51.664,12.471 cw(c51.778,12.471) 51.892,12.471 52.121,12.471 cw(c52.235,12.471) 52.349,12.471 52.578,12.471 v1(52.959,12.471)
DVP-Y9: J4.12 U1.M5 | length 42.6
  Top Layer w0.102: U1.M5@26.024,11.769 26.264,11.53 26.264,10.008 27.991,8.28 v1(30.785,8.28) ; U1.M5@26.027,11.769 U1.M5@26.027,11.772 ; v1(51.968,12.116) 53.442,13.589 56.159,13.589 57.82,15.25 J4.12@58.875,15.25
  Bottom Layer w0.102: v1(30.785,8.28) 32.385,8.28 36.22,12.116 38.557,12.116 cw(c38.672,12.116) 38.786,12.116 ccw(c38.9,12.116) 39.014,12.116 cw(c39.129,12.116) 39.243,12.116 ccw(c39.357,12.116) 39.472,12.116 cw(c39.586,12.116) 39.7,12.116 ccw(c39.814,12.116) 39.929,12.116 cw(c40.043,12.116) 40.157,12.116 ccw(c40.272,12.116) 40.386,12.116 cw(c40.5,12.116) 40.615,12.116 ccw(c40.729,12.116) 40.843,12.116 cw(c40.957,12.116) 41.072,12.116 ccw(c41.186,12.116) 41.3,12.116 cw(c41.415,12.116) 41.529,12.116 ccw(c41.643,12.116) 41.758,12.116 cw(c41.872,12.116) 41.986,12.116 ccw(c42.1,12.116) 42.215,12.116 cw(c42.329,12.116) 42.443,12.116 ccw(c42.558,12.116) 42.672,12.116 cw(c42.786,12.116) 42.901,12.116 ccw(c43.015,12.116) 43.129,12.116 cw(c43.243,12.116) 43.358,12.116 ccw(c43.472,12.116) 43.586,12.116 cw(c43.701,12.116) 43.815,12.116 ccw(c43.929,12.116) 44.044,12.116 cw(c44.158,12.116) 44.272,12.116 ccw(c44.386,12.116) 44.501,12.116 cw(c44.615,12.116) 44.729,12.116 ccw(c44.844,12.116) 44.958,12.116 cw(c45.072,12.116) 45.187,12.116 ccw(c45.301,12.116) 45.415,12.116 cw(c45.529,12.116) 45.644,12.116 ccw(c45.758,12.116) 45.872,12.116 cw(c45.987,12.116) 46.101,12.116 ccw(c46.215,12.116) 46.33,12.116 cw(c46.444,12.116) 46.558,12.116 46.634,12.116 v1(51.968,12.116)
DVP_HSYNC: J4.9 U1.E1 | length 42.7
  Top Layer w0.102: v1(23.063,16.319) U1.E1@23.424,16.319 ; v1(57.81,16.75) J4.9@58.875,16.75
  Bottom Layer w0.102: v1(23.063,16.319) 23.063,16.332 23.393,16.662 23.393,16.784 23.52,16.911 23.52,19.761 24.765,21.006 33.579,21.006 39.192,15.392 56.453,15.392 v1(57.81,16.75)
DVP_PCLK: J4.17 U1.F1 | length 41.2
  Top Layer w0.102: U1.F1@23.424,15.669 23.447,15.646 23.705,15.646 24.01,15.342 v1(24.409,15.342) ; v1(37.719,15.037) 38.786,13.97 v1(55.753,13.97) ; v1(56.974,12.751) J4.17@58.875,12.75
  Bottom Layer w0.102: v1(24.409,15.342) 24.409,15.387 25.603,16.581 25.603,17.272 27.661,19.329 29.515,19.329 cw(c29.629,19.329) 29.743,19.329 ccw(c29.858,19.329) 29.972,19.329 cw(c30.086,19.329) 30.201,19.329 ccw(c30.315,19.329) 30.429,19.329 cw(c30.543,19.329) 30.658,19.329 ccw(c30.772,19.329) 30.886,19.329 30.912,19.329 33.426,19.329 v1(37.719,15.037) ; v1(55.753,13.97) v1(56.974,12.751)
DVP_PWDN: J4.8 U1.E2 | length 44.5
  Top Layer w0.102: v1(23.749,16.002) 23.757,16.002 U1.E2@24.074,16.319 ; J4.8@58.875,17.25 v1(59.871,17.25)
  Bottom Layer w0.102: v1(23.749,16.002) 24.105,16.358 24.105,19.372 25.256,20.523 33.334,20.523 38.897,14.961 57.582,14.961 v1(59.871,17.25)
DVP_RST: J4.6 U1.D2 | length 44.5
  Top Layer w0.102: v1(23.749,16.637) 23.749,16.644 U1.D2@24.074,16.969 U1.D2@24.077,16.972 ; J4.6@58.875,18.25 v1(59.881,18.25)
  Bottom Layer w0.102: v1(23.749,16.637) 23.749,19.304 25.171,20.726 33.418,20.726 38.981,15.164 56.754,15.164 59.84,18.25 v1(59.881,18.25) v1@59.817,18.313
DVP_SCL: J4.5 R39.1 U1.C1 | length 47.9
  Top Layer w0.102: v1(22.936,17.475) 23.28,17.475 U1.C1@23.424,17.619 ; R39.1@57.296,18.212 57.633,18.212 58.171,18.75 J4.5@58.875,18.75 v1(60.152,18.75)
  Bottom Layer w0.102: v1@22.903,17.509 22.987,17.593 22.987,20.803 23.978,21.793 34.163,21.793 39.7,16.256 55.728,16.256 58.222,18.75 v1(60.152,18.75)
DVP_SDA: J4.3 R40.1 U1.C2 | length 48.4
  Top Layer w0.102: v1(22.631,17.907) 23.787,17.907 U1.C2@24.074,17.619 ; R40.1@57.296,20.142 57.688,19.75 J4.3@58.875,19.75 58.886,19.761 v1(59.817,19.761)
  Bottom Layer w0.102: v1(22.631,17.907) 22.631,20.734 23.893,21.996 34.247,21.996 39.784,16.459 55.423,16.459 58.725,19.761 v1(59.817,19.761)
DVP_VSYNC: J4.7 U1.D1 | length 43.3
  Top Layer w0.102: v1(22.962,16.967) 23.422,16.967 U1.D1@23.424,16.969 ; v1(58.014,17.755) 58.87,17.755 J4.7@58.875,17.75
  Bottom Layer w0.102: v1(22.962,16.967) 23.292,17.297 23.292,20.65 24.206,21.565 33.757,21.565 39.37,15.951 55.911,15.951 57.714,17.755 v1(58.014,17.755)
DVP_XCLK: J4.13 U1.F2 | length 42.7
  Top Layer w0.102: U1.F2@24.077,15.672 24.356,15.951 v1(24.359,15.951) ; v1(57.963,14.75) J4.13@58.875,14.75
  Bottom Layer w0.102: v1(24.359,15.951) 24.359,18.466 26.06,20.168 28.804,20.168 cw(c28.918,20.168) 29.032,20.168 ccw(c29.146,20.168) 29.261,20.168 cw(c29.375,20.168) 29.489,20.168 ccw(c29.604,20.168) 29.718,20.168 cw(c29.832,20.168) 29.947,20.168 ccw(c30.061,20.168) 30.175,20.168 cw(c30.29,20.168) 30.404,20.168 ccw(c30.518,20.168) 30.632,20.168 cw(c30.747,20.168) 30.861,20.168 ccw(c30.975,20.168) 31.09,20.168 cw(c31.204,20.168) 31.318,20.168 ccw(c31.432,20.168) 31.547,20.168 cw(c31.661,20.168) 31.775,20.168 ccw(c31.89,20.168) 32.004,20.168 cw(c32.118,20.168) 32.233,20.168 ccw(c32.347,20.168) 32.461,20.168 cw(c32.575,20.168) 32.69,20.168 ccw(c32.804,20.168) 32.918,20.168 32.995,20.168 33.35,20.168 38.786,14.732 57.945,14.732 v1(57.963,14.75)
EN: R32.1 R34.1 U6.7 | length 2
  Top Layer w0.152: R32.1@42.596,5.353 R34.1@43.459,5.353 ; R32.1@42.601,5.358 U6.7@42.601,6.5
GND: C1.2 C2.2 C3.2 C4.2 C5.1 C8.1 C9.2 C10.1 C11.1 C12.1 C13.1 C14.1 C15.1 C16.1 C17.1 C18.1 C19.1 C20.1 C21.1 C22.1 C23.1 C24.1 C25.2 C26.2 C27.2 C28.2 C29.1 C30.2 C31.1 C32.2 C33.1 C34.1 C35.1 C36.2 C37.1 C38.1 C39.1 C40.1 C41.1 C42.1 C43.2 C44.1 C45.1 C46.1 C47.2 C50.1 C51.2 C52.2 C53.1 D1.1 D2.1 DS3.K J1.6 J1.G1 J1.G2 J1.G3 J1.G4 J1.G5 J1.G6 J2.2 J2.3 J3.5 J3.6 J3.7 J3.8 J3.9 J4.15 J4.P0 P1.6 P1.9 P1.14 P1.20 P1.25 P1.30 P1.34 P1.39 P2.18 P2.G P3.2 P5.11 R4.1 R9.2 R11.2 R13.2 R15.2 R19.1 R31.1 R33.2 R49.1 R50.2 TP7.1 U1.C3 U1.C4 U1.C6 U1.C9 U1.C10 U1.D5 U1.D7 U1.D8 U1.E3 U1.E4 U1.E5 U1.E6 U1.E8 U1.E10 U1.F5 U1.F7 U1.F8 U1.F9 U1.F10 U1.G3 U1.G4 U1.G5 U1.G6 U1.G8 U1.H2 U1.H5 U1.H7 U1.H8 U1.H9 U1.J2 U1.J4 U1.J6 U1.J8 U1.J10 U1.K2 U1.K3 U1.K5 U1.K7 U1.K9 U1.K10 U1.L2 U2.1 U3.4 U4.1 U4.4 U4.5 U4.12 U4.13 U4.15 U4.17 U4.21 U5.1 U6.33 U7.2 U7.25 U9.2 X1.2 X1.4 X2.2 X2.4 | length 117.2
  Top Layer w0.152: U1.E3@24.724,16.319 U1.E4@25.374,16.319 U1.D5@26.024,16.969 ; U1.G3@24.727,15.022 U1.G4@25.379,15.022
  Top Layer w0.178: v1(24.397,14.042) 25.057,14.042 U1.J4@25.377,13.722
  Top Layer w0.203: P2.18@16.65,4.333 v1(16.65,5.321) ; v1(21.013,8.782) C8.1@21.013,9.423 ; v1(22.428,7.366) v1(25.197,7.366) 25.469,7.639 C9.2@25.469,7.976 25.756,8.262 25.756,10.587 25.522,10.82 v1(25.476,10.82) ; U1.K2@24.074,13.069 24.093,13.069 v1(24.409,12.753) ; U1.J2@24.077,13.722 v1(24.397,14.042) 24.077,14.362 U1.H2@24.077,14.372 ; 28.956,13.394 U1.K10@29.277,13.072 ; C50.1@34.493,9.925 34.944,9.925 v1(35.077,10.058) ; C51.2@35.077,10.915 v1(35.077,10.058) ; X2.4@35.738,10.058 v1(35.077,10.058) ; v1(43.003,22.302) U4.15@43.345,22.302 ; U4.13@44.145,22.302 44.145,22.631 44.348,22.835 44.545,22.638 U4.12@44.545,22.302 ; U4.4@44.545,19.252 44.545,18.637 44.945,19.037 U4.5@44.945,19.252 ; R50.2@54.845,20.93 54.845,21.825 v1(55.321,22.301)
  Top Layer w0.254: U1.L2@24.079,12.422 v1(24.409,12.753) 24.727,13.07 24.727,13.072 U1.J4@25.374,13.719 25.377,13.722 U1.K5@26.027,13.072 ; U1.C3@24.727,17.622 v1(25.052,17.947) U1.C4@25.377,17.622 ; U1.G4@25.379,15.022 v1(25.694,15.338) ; U1.H5@26.027,14.372 v1(26.352,14.697) ; U1.F5@26.027,15.67 v1(25.694,15.338) ; U1.E5@26.027,16.322 v1(26.351,16.646) ; U1.D5@26.027,16.972 U1.E6@26.677,16.322 ; v1@26.403,12.696 U1.K5@26.027,13.072 ; U1.G6@26.677,15.022 v1(26.352,14.697) ; U1.C6@26.677,17.622 v1(27,17.945) ; U1.H7@27.327,14.372 v1(27.657,14.703) ; U1.F7@27.327,15.672 v1(27.652,15.997) ; U1.D7@27.327,16.972 27.638,16.661 v1(27.666,16.661) U1.D8@27.977,16.972 ; v1@27.652,16.647 27.977,16.322 v1(27.652,15.997) ; U1.H8@27.977,14.372 27.657,14.692 v1(27.657,14.703) ; U1.G8@27.977,15.022 v1(27.657,14.703) ; U1.F8@27.977,15.672 v1(27.652,15.997) ; U1.F9@28.627,15.672 U1.E10@29.277,16.322 ; U1.C9@28.627,17.622 v1(28.952,17.947) U1.C10@29.277,17.622 ; v1@28.882,14.625 28.629,14.372 28.627,14.372 29.277,13.722 28.627,13.072 v1(28.317,13.382) 27.977,13.722 27.327,13.072 v1(27,13.399) 26.677,13.722 U1.K5@26.027,13.072 ; v1(28.954,15.995) U1.F10@29.277,15.672 ; C51.2@35.11,10.947 35.11,11.234 35.502,11.626 v1(36.271,11.626) ; U4.17@42.62,21.177 43.745,21.177 v1(44.145,20.777) ; v1(55.804,17.348) C45.1@56.446,17.348 ; v1(57.895,13.75) J4.15@58.875,13.75 v1(59.826,13.75) ; v1(58.09,8.534) 59.563,8.534 59.826,8.797 ; v1(25.694,15.338) 25.712,15.338 v1(26.352,14.697)
  Top Layer w0.406: v1(0.72,19.295) J1.6@1.839,19.295 ; v1(14.993,18.244) U3.4@15.596,18.244 ; v1(20.523,17.755) C14.1@21.114,17.755 C11.1@21.114,16.891 C21.1@21.114,16.027 ; v1(20.65,14.249) C5.1@21.114,14.249 ; C13.1@21.114,20.168 21.114,20.606 21.311,20.803 22.841,20.803 C4.2@23.527,20.117 ; C19.1@26.365,22.193 26.524,22.352 v1(27.076,22.352) ; v1(40.379,20.44) C33.1@40.379,21.006 C32.2@40.379,21.819 ; v1(40.379,22.359) C32.2@40.379,21.819 ; v1(41.802,21.837) C27.2@41.275,21.837 40.398,21.837 C32.2@40.379,21.819 ; R13.2@42.469,16.898 R9.2@43.332,16.898 ; v1(50.419,19.939) 51.919,19.939 v1(52.197,20.217) ; U5.1@54.998,14.874 55.916,14.874 v1(56.413,14.376) 56.849,14.812 56.849,14.912 C47.2@56.007,15.755 ; J3.5@55.3,4.18 55.3,5.371 D1.1@55.518,5.588 ; v1(55.753,8.839) 56.09,8.503 R33.2@56.446,8.503
  Top Layer w0.508: C46.1@18.549,9.423 R4.1@18.549,10.262 C24.1@18.549,11.074 ; v1(21.114,19.692) C13.1@21.114,20.168 ; v1@27.076,22.301 27.076,21.482 C17.1@27.229,21.329 C2.2@28.143,21.329 ; C22.1@32.785,11.125 C23.1@32.785,11.963 ; C12.1@32.785,15.57 C10.1@32.785,16.383 C15.1@32.785,17.17 ; C18.1@32.785,19.329 v1(32.785,18.923) C16.1@32.785,18.491 ; v1(33.249,18.491) C16.1@32.785,18.491 ; v1(33.299,12.802) C20.1@32.785,12.802 C23.1@32.785,11.963 ; v1(33.376,12.192) 33.147,11.963 C23.1@32.785,11.963 ; C3.2@33.63,17.189 v1(33.63,17.729) ; C1.2@34.449,17.17 C15.1@32.785,17.17 ; C1.2@34.468,17.189 v1(34.976,17.189) ; C52.2@35.11,7.061 R15.2@35.11,8.026 ; C38.1@36.837,8.026 36.837,8.313 X2.2@37.465,8.941 ; C40.1@41.7,4.496 C39.1@41.7,5.359 ; C28.2@47.041,20.606 C29.1@47.904,20.606 ; C30.2@47.904,17.748 C31.1@47.041,17.748 v1(47.041,18.339) C26.2@47.041,18.93 C25.2@47.904,18.93 ; v1(52.197,20.217) C36.2@52.197,21.952 ; C35.1@57.296,5.588 v1(57.785,5.588) ; C34.1@57.296,6.56 v1(57.766,6.56) ; C15.1@32.785,17.17 v1(32.785,17.78) C16.1@32.785,18.491
  Top Layer w0.762: v1(50.419,21.209) v1(50.419,19.939) U9.2@50.419,18.939 v1(50.419,18.263) 50.419,18.093 C53.1@51.011,17.501 v1(51.841,17.501)
  Bottom Layer w0.102: v1@56.286,14.503 v1(56.413,14.376)
  Bottom Layer w0.127: v1(36.817,14.643) 36.957,14.503 v1@56.286,14.503
  other v1: 25.527,0.483 12.979,0.991 33.35,0.991 16.586,1.016 34.341,1.245 10.084,1.27 33.477,1.549 8.585,1.626 25.527,1.905 33.858,1.93 14.326,1.956 15.545,1.956 18.364,1.956 23.927,1.981 47.777,2.972 28.473,3.429 29.235,3.429 11.633,3.531 12.852,3.531 38.481,3.886 39.446,3.886 31.344,3.934 32.029,3.934 32.69,3.934 37.236,4.166 35.89,4.293 39.7,4.293 37.262,4.674 37.998,4.674 39.802,4.801 35.738,4.851 30.529,4.877 41.707,4.928 27.686,4.953 19.05,5.156 45.237,5.258 22.682,5.309 51.257,5.613 13.614,5.731 47.346,5.766 37.516,6.121 38.1,6.121 29.743,6.35 33.63,6.35 29.083,6.375 20.574,6.452 31.344,6.734 32.029,6.734 32.69,6.734 22.911,6.807 39.167,6.807 59.182,6.858 29.845,7.137 39.851,7.5 42.851,7.5 35.11,7.544 32.283,7.747 45.923,7.899 34.544,8.407 36.855,8.458 52.73,8.966 41.351,9 25.044,9.093 33.858,9.22 62.027,9.296 59.826,9.5 17.856,9.627 23.317,10.211 57.125,10.236 39.851,10.5 42.851,10.5 4.47,10.566 56.617,10.744 23.774,10.897 24.638,10.897 54.712,10.973 17.882,11.049 11.7,11.16 60.757,11.328 47.066,11.582 55.321,11.659 52.273,11.684 52.807,11.963 16.307,12.04 17.501,12.243 54.534,12.319 53.594,12.421 18.796,12.522 59.944,12.675 26.365,12.721 15.011,13.106 59.969,13.233 0.787,13.31 2.972,13.945 57.379,14.275 4.775,14.63 28.88,14.626 12.675,14.66 59.868,14.732 17.501,15.344 3.226,15.469 15.011,15.469 0.762,15.951 35.941,16.205 60.935,16.307 10.185,16.662 42.901,16.898 7.442,17.247 40.005,17.247 15.011,17.323 53.848,17.348 16.358,17.501 40.742,17.755 47.473,17.748 38.964,17.907 40.208,18.009 5.74,18.11 8.433,18.136 17.501,18.161 16.231,18.313 18.771,18.339 42.189,18.466 44.526,18.618 43.18,18.694 46.253,19.025 3.353,19.152 8.077,19.202 38.557,19.202 37.668,19.634 38.608,20.091 43.612,20.295 44.679,20.295 0.762,20.396 61.544,20.447 47.473,20.599 12.675,20.63 6.071,20.955 43.18,21.184 52.197,21.234 43.637,21.311 44.679,21.311 59.004,22.047 9.855,22.225 7.188,22.327 31.623,22.352 0.737,22.555 44.348,22.758 48.59,23.089
I2C_SCL: P1.5 P1.28 P2.2 R6.1 U1.B5 | length 61.3
  Top Layer w0.102: v1(25.687,17.932) U1.B5@26.024,18.269 U1.B5@26.027,18.272
  Top Layer w0.152: P2.2@8.65,4.333 R6.1@8.65,5.56 ; R6.1@8.821,5.731 R6.1@8.65,5.56 ; v1(9.754,18.034) 9.754,9.55 8.65,8.447 R6.1@8.65,5.56
  MidLayer1 w0.102: v1(25.687,17.932) 26.171,17.932 26.695,18.457 26.695,24.079 27.381,24.765 27.381,25.654 28.219,26.492 40.112,26.492 P1.28@41.39,27.77
  Bottom Layer w0.102: P1.5@13.45,25.23 14.829,23.851 26.467,23.851 v1(26.848,24.232)
  Bottom Layer w0.152: v1(9.754,18.034) 9.754,21.534 P1.5@13.45,25.23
